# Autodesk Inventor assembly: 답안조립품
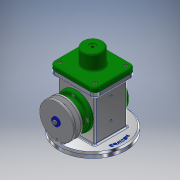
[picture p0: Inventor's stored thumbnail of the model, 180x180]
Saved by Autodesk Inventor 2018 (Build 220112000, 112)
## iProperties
Created: 2019-08
Part Number: 답안조립품
Material: 일반
Document SubType Name: Assembly
Designer: USER
Author: USER
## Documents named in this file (18)
- C:\Users\USER\Desktop\490804V1010\답안조립품.iam
- C:\Users\USER\Desktop\490804V1010\본체.ipt
- C:\Users\USER\Desktop\490804V1010\E-링.ipt
- C:\Users\USER\Desktop\490804V1010\V-벨트풀리.ipt
- C:\Users\USER\Desktop\490804V1010\덮개.ipt
- C:\Users\USER\Desktop\490804V1010\뒤커버.ipt
- C:\Users\USER\Desktop\490804V1010\링크.ipt
- C:\Users\USER\Desktop\490804V1010\베어링 17 x 40 x 12.ipt
- C:\Users\USER\Desktop\490804V1010\볼트 M4 x 8.ipt
- C:\Users\USER\Desktop\490804V1010\볼트 M4 x 10.ipt
- C:\Users\USER\Desktop\490804V1010\슬라이더.ipt
- C:\Users\USER\Desktop\490804V1010\앞커버.ipt
- C:\Users\USER\Desktop\490804V1010\오일 실 17 30 8.ipt
- C:\Users\USER\Desktop\490804V1010\와셔 4x16.ipt
- C:\Users\USER\Desktop\490804V1010\클레비스 핀 6 x 22.ipt
- 클레비스 핀 6 x 22.ipt
- C:\Users\USER\Desktop\490804V1010\키 4 x 4 x 12.ipt
- C:\Users\USER\Desktop\490804V1010\편심축.ipt
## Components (2 placed, 2 different names)
1. E-링:1
2. V-벨트풀리:1
